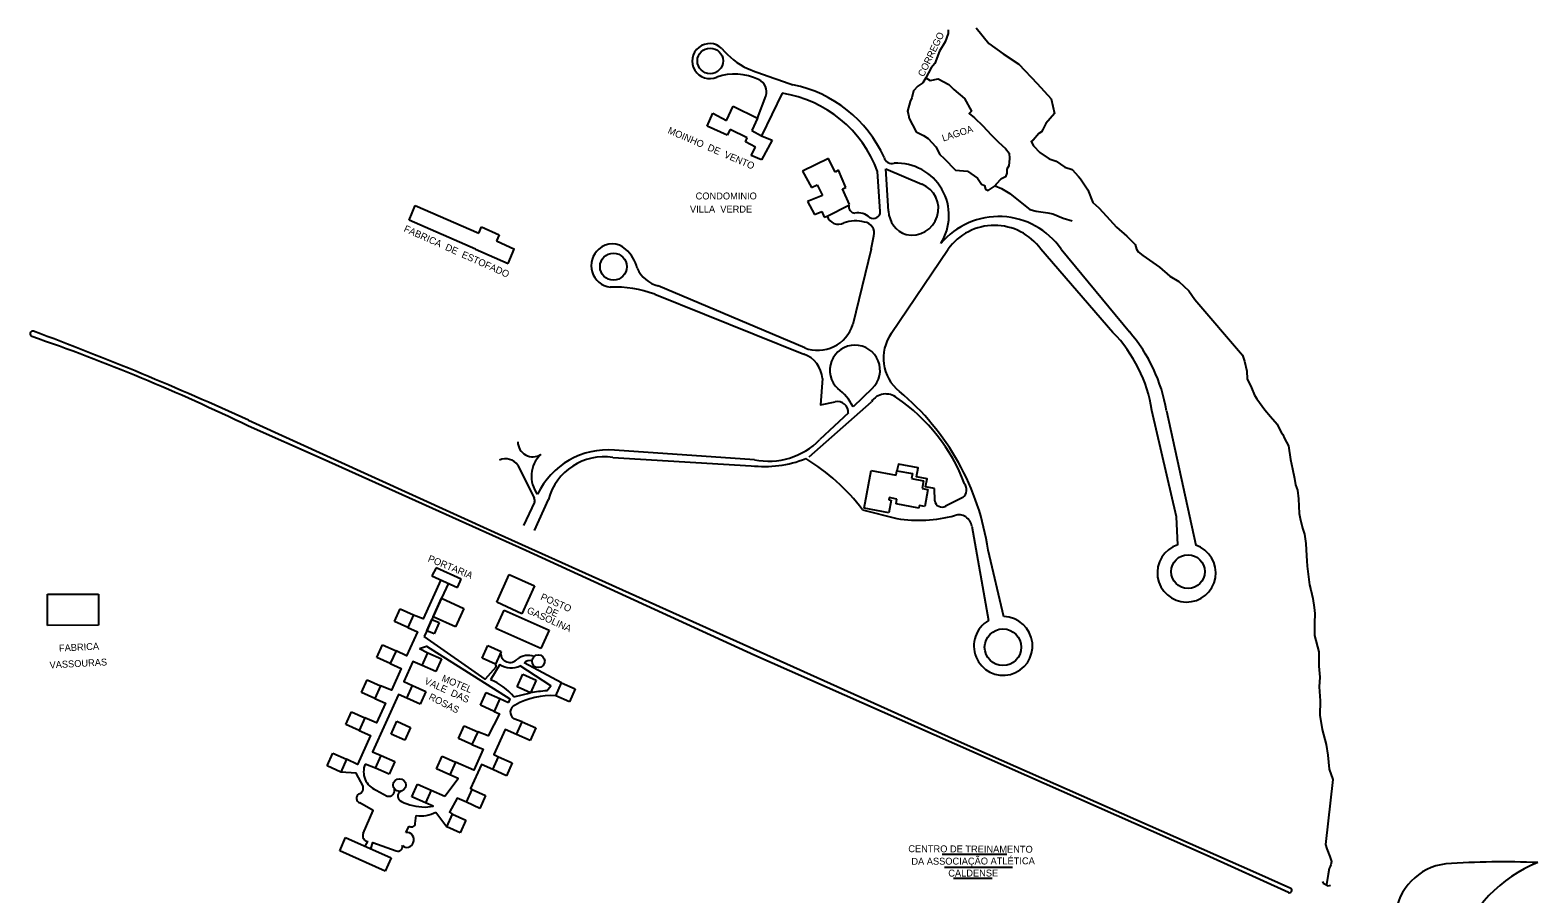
# Model space of a CAD drawing. Extents: x 325899 to 364828, y 7568995 to 7592502.
# Drawn here: x 344755 to 345627, y 7588130 to 7588628 of the extents above; entities that cross this region are included whole.
import ezdxf

# ---------------------------------------------------------------- set-up
doc = ezdxf.new("R2010")
doc.units = 0
for name, color, linetype in [('EDIFEXISTENT', 7, 'Continuous'), ('EDIFIDENTIF', 7, 'Continuous'), ('EDIFOBRAEXIS', 7, 'Continuous')]:
    doc.layers.add(name, color=color, linetype=linetype)

msp = doc.modelspace()

# ---------------------------------------------------------------- linework, layer by layer
at = {"layer": 'EDIFEXISTENT'}
for p, q in [((345157.69, 7588576.3), (345161.49, 7588584.55)), ((345161.49, 7588584.55), (345175.64, 7588577.68)), ((345146.54, 7588573.03), (345149.87, 7588580.41)), ((345149.87, 7588580.41), (345157.69, 7588576.3)), ((345175.64, 7588577.68), (345172.36, 7588570.43)), ((345158.02, 7588567.72), (345146.54, 7588573.03)), ((345159.79, 7588571.08), (345158.02, 7588567.72)), ((345169.69, 7588566.19), (345159.79, 7588571.08)), ((345172.36, 7588570.43), (345177.98, 7588567.43)), ((345177.98, 7588567.43), (345184.13, 7588564.95)), ((345168.59, 7588563.88), (345169.69, 7588566.19)), ((345174.46, 7588560.91), (345168.59, 7588563.88)), ((345171.95, 7588556.01), (345174.46, 7588560.91)), ((345184.13, 7588564.95), (345177.89, 7588553.63)), ((345177.89, 7588553.63), (345171.95, 7588556.01)), ((345216.7, 7588554.36), (345201.7, 7588547.03)), ((345220.47, 7588546.44), (345216.7, 7588554.36)), ((345201.7, 7588547.03), (345206.77, 7588537.63)), ((345222.41, 7588547.62), (345220.47, 7588546.44)), ((345226.73, 7588537.6), (345222.41, 7588547.62)), ((345213.18, 7588532.97), (345204.53, 7588529.38)), ((345206.77, 7588537.63), (345210.15, 7588539.19)), ((345210.15, 7588539.19), (345213.18, 7588532.97)), ((345224.66, 7588536.75), (345226.73, 7588537.6)), ((345228.81, 7588527.72), (345224.66, 7588536.75)), ((344974.25, 7588518.76), (344977.88, 7588527.11)), ((344977.88, 7588527.11), (345014.57, 7588511.18)), ((345204.53, 7588529.38), (345208.57, 7588521.96)), ((345208.57, 7588521.96), (345212.84, 7588523.73)), ((345212.84, 7588523.73), (345214.06, 7588520.48)), ((345215.88, 7588520.99), (345228.41, 7588527.26)), ((345228.41, 7588527.26), (345228.81, 7588527.72)), ((345012.71, 7588501.91), (344974.25, 7588518.76)), ((345014.57, 7588511.18), (345016.17, 7588514.84)), ((345016.17, 7588514.84), (345026.36, 7588510.27)), ((345214.06, 7588520.48), (345215.88, 7588520.99)), ((345026.36, 7588510.27), (345024.71, 7588506.83)), ((345024.71, 7588506.83), (345035.23, 7588501.91)), ((345012.71, 7588501.91), (345031.59, 7588493.67)), ((345031.59, 7588493.67), (345035.09, 7588501.91)), ((345237.25, 7588352.41), (345241.29, 7588374.03)), ((345241.29, 7588374.03), (345255.71, 7588371.34)), ((345255.71, 7588371.34), (345256.2, 7588373.99)), ((345256.2, 7588373.99), (345265.11, 7588372.33)), ((345265.11, 7588372.33), (345264.58, 7588369.48)), ((345264.58, 7588369.48), (345271.61, 7588368.17)), ((345271.61, 7588368.17), (345270.77, 7588363.7)), ((345251.73, 7588358.42), (345251.49, 7588357.17)), ((345256.21, 7588357.59), (345251.73, 7588358.42)), ((345270.77, 7588363.7), (345274.14, 7588363.07)), ((345274.14, 7588363.07), (345272.33, 7588353.38)), ((345251.55, 7588349.74), (345237.25, 7588352.41)), ((345251.49, 7588357.17), (345252.78, 7588356.93)), ((345252.78, 7588356.93), (345251.55, 7588349.74)), ((345255.69, 7588354.8), (345256.21, 7588357.59)), ((345268.83, 7588352.35), (345255.69, 7588354.8)), ((345269.13, 7588353.98), (345268.83, 7588352.35)), ((345272.33, 7588353.38), (345269.13, 7588353.98)), ((344989.92, 7588317.83), (344987.47, 7588313.21)), ((345004.36, 7588311.37), (344989.92, 7588317.83)), ((344987.47, 7588313.21), (345002.23, 7588306.6)), ((345002.23, 7588306.6), (345002.38, 7588306.94)), ((345002.38, 7588306.94), (345004.36, 7588311.37)), ((345025.03, 7588298.05), (345032.15, 7588313.96)), ((345032.15, 7588313.96), (345046.73, 7588307.44)), ((345046.73, 7588307.44), (345039.53, 7588291.36)), ((344765.39, 7588284.56), (344765.28, 7588302.65)), ((344765.28, 7588302.65), (344794.85, 7588302.61)), ((344794.85, 7588302.61), (344794.77, 7588284.68)), ((344988.19, 7588289.56), (344992.99, 7588300.28)), ((344992.99, 7588300.28), (345005.95, 7588294.48)), ((345039.53, 7588291.36), (345025.03, 7588298.05)), ((344965.84, 7588286.82), (344969.12, 7588294.17)), ((344969.12, 7588294.17), (344976.91, 7588290.68)), ((344976.91, 7588290.68), (344973.62, 7588283.34)), ((345001.15, 7588283.76), (344988.19, 7588289.56)), ((345005.95, 7588294.48), (345001.15, 7588283.76)), ((345024.46, 7588282.89), (345029.22, 7588293.52)), ((345029.22, 7588293.52), (345055.23, 7588281.88)), ((344794.77, 7588284.68), (344765.39, 7588284.56)), ((344973.62, 7588283.34), (344965.84, 7588286.82)), ((344984.52, 7588281.51), (344987.47, 7588288.12)), ((344988.68, 7588279.85), (344984.52, 7588281.51)), ((344987.47, 7588288.12), (344991.57, 7588286.29)), ((344991.57, 7588286.29), (344988.68, 7588279.85)), ((345050.39, 7588271.29), (345024.46, 7588282.89)), ((345055.23, 7588281.88), (345050.39, 7588271.29)), ((344955.66, 7588266.05), (344958.94, 7588273.4)), ((344958.94, 7588273.4), (344966.73, 7588269.91)), ((345016.45, 7588265.65), (345019.73, 7588273)), ((345019.73, 7588273), (345027.52, 7588269.51)), ((344963.44, 7588262.57), (344955.66, 7588266.05)), ((344966.73, 7588269.91), (344963.44, 7588262.57)), ((344981.87, 7588261.42), (344985.15, 7588268.77)), ((344985.15, 7588268.77), (344992.94, 7588265.28)), ((344992.94, 7588265.28), (344989.65, 7588257.94)), ((345024.23, 7588262.17), (345016.45, 7588265.65)), ((345027.52, 7588269.51), (345024.23, 7588262.17)), ((344989.65, 7588257.94), (344981.87, 7588261.42)), ((345036.69, 7588249.21), (345039.97, 7588256.55)), ((345039.97, 7588256.55), (345047.76, 7588253.07)), ((344946.72, 7588245.93), (344950, 7588253.28)), ((344954.5, 7588242.45), (344946.72, 7588245.93)), ((344950, 7588253.28), (344957.78, 7588249.79)), ((344957.78, 7588249.79), (344954.5, 7588242.45)), ((344972.92, 7588242.63), (344976.2, 7588249.97)), ((344976.2, 7588249.97), (344983.98, 7588246.49)), ((344983.98, 7588246.49), (344980.7, 7588239.14)), ((345015.64, 7588238.49), (345018.92, 7588245.83)), ((345018.92, 7588245.83), (345026.71, 7588242.35)), ((345044.47, 7588245.72), (345036.69, 7588249.21)), ((345047.76, 7588253.07), (345044.47, 7588245.72)), ((345059.14, 7588244.05), (345062.42, 7588251.4)), ((345062.42, 7588251.4), (345070.21, 7588247.91)), ((345070.21, 7588247.91), (345066.92, 7588240.57)), ((344980.7, 7588239.14), (344972.92, 7588242.63)), ((345023.43, 7588235), (345015.64, 7588238.49)), ((345026.71, 7588242.35), (345023.43, 7588235)), ((345066.92, 7588240.57), (345059.14, 7588244.05)), ((344937.73, 7588227.44), (344941.01, 7588234.79)), ((344945.52, 7588223.96), (344937.73, 7588227.44)), ((344941.01, 7588234.79), (344948.8, 7588231.3)), ((344948.8, 7588231.3), (344945.52, 7588223.96)), ((344963.95, 7588221.9), (344967.23, 7588229.24)), ((344967.23, 7588229.24), (344975.02, 7588225.76)), ((345036.37, 7588221.56), (345039.65, 7588228.9)), ((345039.65, 7588228.9), (345047.44, 7588225.42)), ((344971.74, 7588218.41), (344963.95, 7588221.9)), ((344975.02, 7588225.76), (344971.74, 7588218.41)), ((345002.85, 7588219.37), (345006.13, 7588226.72)), ((345010.63, 7588215.89), (345002.85, 7588219.37)), ((345006.13, 7588226.72), (345013.92, 7588223.23)), ((345013.92, 7588223.23), (345010.63, 7588215.89)), ((345044.16, 7588218.08), (345036.37, 7588221.56)), ((345047.44, 7588225.42), (345044.16, 7588218.08)), ((344926.97, 7588203.44), (344930.25, 7588210.78)), ((344930.25, 7588210.78), (344938.04, 7588207.3)), ((344934.75, 7588199.95), (344926.97, 7588203.44)), ((344938.04, 7588207.3), (344934.75, 7588199.95)), ((344954.93, 7588202.13), (344958.21, 7588209.48)), ((344962.72, 7588198.65), (344954.93, 7588202.13)), ((344958.21, 7588209.48), (344966, 7588205.99)), ((344966, 7588205.99), (344962.72, 7588198.65)), ((344990.11, 7588201.84), (344993.39, 7588209.18)), ((344997.9, 7588198.36), (344990.11, 7588201.84)), ((344993.39, 7588209.18), (345001.18, 7588205.7)), ((345001.18, 7588205.7), (344997.9, 7588198.36)), ((345022.7, 7588201.32), (345025.98, 7588208.66)), ((345030.48, 7588197.83), (345022.7, 7588201.32)), ((345025.98, 7588208.66), (345033.77, 7588205.18)), ((345033.77, 7588205.18), (345030.48, 7588197.83)), ((344975.91, 7588185.69), (344979.19, 7588193.03)), ((344979.19, 7588193.03), (344986.98, 7588189.55)), ((344983.7, 7588182.21), (344975.91, 7588185.69)), ((344986.98, 7588189.55), (344983.7, 7588182.21)), ((345007.46, 7588182.46), (345010.74, 7588189.8)), ((345010.74, 7588189.8), (345018.53, 7588186.32)), ((345018.53, 7588186.32), (345015.24, 7588178.98)), ((344996.04, 7588168.25), (344999.32, 7588175.59)), ((344999.32, 7588175.59), (345007.11, 7588172.11)), ((345015.24, 7588178.98), (345007.46, 7588182.46)), ((345003.82, 7588164.76), (344996.04, 7588168.25)), ((345007.11, 7588172.11), (345003.82, 7588164.76)), ((344934.2, 7588154.44), (344937.57, 7588162.18)), ((344937.57, 7588162.18), (344963.91, 7588150.39)), ((344960.49, 7588142.68), (344934.2, 7588154.44)), ((344963.91, 7588150.39), (344960.49, 7588142.68)), ((345502.19, 7588136.74), (345502.56, 7588135.78)), ((345502.56, 7588135.78), (345505.45, 7588134.28)), ((345505.45, 7588134.28), (345506.79, 7588134.62))]:
    msp.add_line(p, q, dxfattribs=at)
for centre in [(345049.04, 7588263.97), (344968.74, 7588192.42)]:
    msp.add_circle(centre, 3.67, dxfattribs=at)
at = {"layer": 'EDIFIDENTIF'}
msp.add_circle((345148.29, 7588610.68), 7.4, dxfattribs=at)
at = {"layer": 'EDIFOBRAEXIS'}
for points in [[(345285.76, 7588628.53), (345285.77, 7588626.47), (345284, 7588621.78), (345280.77, 7588616.26), (345278.09, 7588609.17), (345275.9, 7588606.69), (345272.9, 7588600.82), (345275.44, 7588599.31), (345279.95, 7588600.26), (345286.24, 7588597.06), (345288.98, 7588594.21), (345295.33, 7588589.01), (345299.32, 7588581.66), (345298, 7588580.34), (345301.07, 7588577.7), (345305.92, 7588573.26), (345310.72, 7588567.98), (345314.94, 7588563.78), (345318.97, 7588560.01), (345321.12, 7588557.48), (345321.28, 7588554.23), (345320.92, 7588550.01), (345319.71, 7588548.13), (345319.72, 7588545.92), (345318.87, 7588543.72), (345316.25, 7588542.35), (345315.73, 7588541.71), (345314.06, 7588540.05), (345313.28, 7588539.27), (345312.99, 7588538.43), (345316.6, 7588536.99), (345321.43, 7588534.08), (345328.44, 7588528.56), (345333.06, 7588524.85), (345336.74, 7588523.9), (345343.36, 7588522.97), (345346.37, 7588522.39), (345352.19, 7588519.85), (345357.55, 7588518.34)], [(345301.98, 7588629.7), (345309.34, 7588620.68), (345317.55, 7588614.67), (345326.63, 7588608.73), (345337.22, 7588597.63), (345345.28, 7588588.72), (345347.16, 7588580.21), (345342.25, 7588574.46), (345340.51, 7588570.97), (345339.82, 7588569.68), (345338.13, 7588568.74), (345334.9, 7588564.92), (345334.55, 7588564.63), (345333.82, 7588564.06), (345335.16, 7588561.6), (345338.79, 7588557.69), (345344.19, 7588554.08), (345348.13, 7588552.72), (345353.22, 7588549.23), (345357.44, 7588547.98), (345361.09, 7588543.95), (345362.21, 7588542.47), (345366.46, 7588536.29), (345369.36, 7588528.89), (345372.85, 7588525.85), (345377.36, 7588521), (345383.11, 7588514.72), (345389.05, 7588509.54), (345393.89, 7588504.56), (345394.61, 7588501.91), (345394.61, 7588501.91)], [(345272.9, 7588600.82), (345271.1, 7588597.99), (345268.33, 7588596.04), (345265.76, 7588593.35), (345264.74, 7588589.31), (345263.89, 7588587.19), (345262.36, 7588581.72), (345262.88, 7588579.62), (345263.35, 7588577.37), (345265.16, 7588573.76), (345267.4, 7588569.63), (345271.53, 7588567.67), (345274.33, 7588565.82), (345278.66, 7588560.99), (345280.9, 7588556.63), (345283.58, 7588554.21), (345290.05, 7588547.53), (345297, 7588547.02), (345302.74, 7588543.03), (345305.14, 7588539.44), (345306.79, 7588538.63), (345307.46, 7588536.5), (345308.92, 7588535.82), (345312.99, 7588538.43)], [(345175.64, 7588577.68), (345180.5, 7588590.38)], [(345189.88, 7588591.97), (345177.98, 7588567.43)], [(345246.6, 7588523.61), (345245.05, 7588546.72)], [(345249.82, 7588548.33), (345270.55, 7588539.49)], [(345251.34, 7588523.88), (345249.82, 7588548.33)], [(345241.34, 7588501.91), (345242.83, 7588509.71)], [(345241.34, 7588501.91), (345230.69, 7588458.43)], [(345252.92, 7588453.3), (345285.78, 7588501.91)], [(345381.02, 7588453.89), (345339.35, 7588501.91)], [(345351.11, 7588501.91), (345390.53, 7588454.21)], [(345394.61, 7588501.91), (345395.62, 7588500.41), (345398.25, 7588498.33), (345407.91, 7588491.57), (345413.81, 7588486.38), (345419.06, 7588483.28), (345424.89, 7588477.81), (345428.28, 7588472.88), (345455.85, 7588440.8), (345457.03, 7588437.17), (345458.36, 7588431.43), (345458.53, 7588426.98), (345461.13, 7588421.94), (345462.85, 7588417.53), (345464.17, 7588415.55), (345468.84, 7588409.13), (345471.98, 7588405.37), (345475.84, 7588400.95), (345478.52, 7588395.2), (345479.13, 7588394.93), (345480.15, 7588392.67), (345482.45, 7588388.29), (345483.68, 7588380.52), (345484.8, 7588375.16), (345485.95, 7588369.44), (345486.59, 7588365.78), (345487.59, 7588362.79), (345488.33, 7588357.68), (345488.69, 7588349.26), (345489.3, 7588346.46), (345490.55, 7588340.85), (345491.63, 7588337.37), (345492.45, 7588331.96), (345492.92, 7588324.86), (345493.03, 7588321.88), (345493.19, 7588318.78), (345493.87, 7588314.23), (345494.56, 7588308.03), (345495.43, 7588305.11), (345496.6, 7588300.13), (345497.26, 7588295.02), (345497.78, 7588291.59), (345497.4, 7588285.98), (345497.57, 7588278.78), (345499.96, 7588269.39), (345500.09, 7588261.17), (345500.56, 7588254.83), (345500.15, 7588249.23), (345500.77, 7588241.14), (345500.67, 7588232.74), (345501.97, 7588224.43), (345504.22, 7588215.9), (345505.25, 7588209.67), (345505.96, 7588201.66), (345508.13, 7588195.57), (345503.89, 7588158.09), (345504.71, 7588155.68), (345506.28, 7588151.16), (345507.27, 7588148.3), (345506.88, 7588146.28), (345506.49, 7588145.39), (345506.01, 7588144.14), (345505.43, 7588140.97), (345504.46, 7588134.94), (345504.46, 7588134.94)], [(345202.88, 7588444.94), (345118.22, 7588480.7)], [(345116.2, 7588475.9), (345202.4, 7588441.24)], [(345213.12, 7588427.26), (345212.05, 7588412), (345220.56, 7588413.84)], [(345241.94, 7588421.51), (345230.82, 7588410.83)], [(345205.55, 7588382.05), (345241.41, 7588413.86)], [(344881.39, 7588403.14), (345025.72, 7588337.48), (345293.6, 7588217.05), (345463.58, 7588141.91), (345483.86, 7588132.84)], [(345228.11, 7588407.42), (345211.61, 7588391.94)], [(345418.54, 7588331.11), (345417.67, 7588347.42), (345403.55, 7588408.8)], [(345411.93, 7588408.58), (345428.9, 7588331.01)], [(345482.39, 7588130.34), (345434.87, 7588151.92), (345174.01, 7588267.28), (345041.67, 7588327.94), (344924.14, 7588380.88), (344881.39, 7588399.73)], [(345173.8, 7588380.34), (345093, 7588385.84)], [(345037.11, 7588377.13), (345046.54, 7588358.13)], [(345092.05, 7588381.58), (345171.97, 7588376.89)], [(345277.99, 7588363.72), (345272.77, 7588364.69), (345273.62, 7588369.22), (345267.47, 7588370.37), (345268.44, 7588375.57), (345257.04, 7588377.7), (345256.2, 7588373.99)], [(345278.01, 7588356.62), (345277.99, 7588363.72)], [(345294.28, 7588358.59), (345284.35, 7588353.42)], [(345046.77, 7588355.76), (345040.31, 7588342.38)], [(345046.78, 7588339.43), (345054.89, 7588357.44)], [(345236.34, 7588351.48), (345256.14, 7588346.36)], [(345299.46, 7588341.91), (345309.18, 7588287.43)], [(345318.04, 7588289.68), (345308.83, 7588328.16)], [(344992.61, 7588310.91), (344982.47, 7588288.49), (344976.9, 7588290.63)], [(344996.97, 7588308.95), (344992.99, 7588300.28), (344987.47, 7588288.12), (344984.52, 7588281.51), (344983.07, 7588278.32)], [(344973.62, 7588283.34), (344979.08, 7588280.87), (344972.82, 7588267.03), (344966.73, 7588269.91)], [(344980.29, 7588271.24), (344984.43, 7588272.58), (345032.42, 7588242.27), (345031.71, 7588240.09)], [(344980.29, 7588271.24), (344985.15, 7588268.77)], [(345024.38, 7588260.52), (345018.29, 7588253.51), (344983.07, 7588278.32)], [(344963.44, 7588262.57), (344969.75, 7588259.72), (344964.1, 7588247.22), (344957.78, 7588249.79)], [(344981.87, 7588261.42), (344976.49, 7588263.86), (344971.26, 7588252.28), (344976.2, 7588249.97)], [(345062.42, 7588251.4), (345040.85, 7588263.02)], [(345026.73, 7588262.02), (345021.34, 7588253.24)], [(345053.84, 7588246.86), (345056.17, 7588249.81), (345038.55, 7588261.32)], [(344972.92, 7588242.63), (344968.1, 7588244.8), (344953.05, 7588211.53), (344958.21, 7588209.48)], [(345034.88, 7588243.47), (345044.47, 7588245.72)], [(344954.5, 7588242.45), (344960.59, 7588239.7), (344955.48, 7588228.41), (344948.8, 7588231.3)], [(345026.71, 7588242.35), (345031.71, 7588240.09)], [(345023.43, 7588235), (345026.61, 7588233.64), (345020.04, 7588220.9), (345013.92, 7588223.23)], [(345039.65, 7588228.9), (345034.88, 7588230.74)], [(344945.52, 7588223.96), (344952.05, 7588221.01), (344944.49, 7588204.3), (344938.04, 7588207.3)], [(345036.37, 7588221.56), (345029.83, 7588224.52), (345023.32, 7588210.12), (345025.98, 7588208.66)], [(345010.63, 7588215.89), (345017.05, 7588213.13), (345011.67, 7588200.99), (345001.18, 7588205.7)], [(344954.93, 7588202.13), (344948.87, 7588204.58)], [(345022.7, 7588201.32), (345016.1, 7588204.3), (345009.83, 7588190.44), (345010.74, 7588189.8)], [(344947.67, 7588191.73), (344943.73, 7588199.23), (344934.75, 7588199.95)], [(344994.89, 7588185.97), (345002.61, 7588196.22), (344997.9, 7588198.36)], [(344955.23, 7588189.49), (344961.7, 7588186.04)], [(344986.98, 7588189.55), (344994.89, 7588185.97)], [(345007.46, 7588182.46), (345002.11, 7588184.87), (344997.57, 7588176.84), (344999.32, 7588175.59)], [(344947.83, 7588164.37), (344953.56, 7588177.64), (344945.81, 7588182.09)], [(344983.49, 7588179.7), (344988.2, 7588180.14), (344983.7, 7588182.21)], [(344989.71, 7588176.82), (344996.04, 7588168.25)], [(344972.37, 7588164.99), (344974.26, 7588168.7)], [(344977.86, 7588170.16), (344978.38, 7588174.78)], [(344948.95, 7588157.09), (344950.37, 7588159.92)], [(344952.13, 7588155.66), (344953.28, 7588159.33), (344966.82, 7588154.43)], [(345282.3, 7588152.43), (345319.69, 7588152.43)], [(345283.63, 7588144.95), (345322.92, 7588144.95)], [(345288.92, 7588138.63), (345311.25, 7588138.63)]]:
    msp.add_lwpolyline(points, dxfattribs=at)
for centre, radius in [((345092.38, 7588491.83), 7.76), ((345424.4, 7588315.7), 9.73), ((345317.48, 7588272.01), 10.6)]:
    msp.add_circle(centre, radius, dxfattribs=at)
for centre, radius, start, end in [((345147.99, 7588610.59), 10.12, 46.03268, 294.01233), ((345188.23, 7588644.97), 42.86, 219.20323, 244.56676), ((345162.44, 7588570.35), 32.66, 64.91761, 108.43206), ((345392.55, 7589189.34), 624.18, 249.09402, 251.65702), ((345172.84, 7588592.71), 8, 343.10031, 64.54014), ((345181.19, 7588524.06), 74.34, 24.6302, 78.41161), ((345179.28, 7588522.79), 69.99, 19.99599, 81.28925), ((345253.27, 7588555.91), 4.59, 190.94063, 287.52506), ((345256.07, 7588521.39), 30.18, 327.39844, 92.70588), ((345264.9, 7588525.29), 15.28, 257.49473, 68.31362), ((345232.24, 7588526.57), 3.89, 169.7853, 264.54072), ((345242.69, 7588523.56), 3.91, 236.78135, 0.85547), ((345266.05, 7588524.4), 14.72, 182.01248, 252.35369), ((345222.34, 7588523.16), 6.81, 198.55205, 297.6243), ((345232.18, 7588498.21), 20.06, 74.684, 109.45111), ((345233.8, 7588512.83), 10.05, 47.84917, 101.08842), ((345236.77, 7588511.32), 6.28, 345.18709, 83.50259), ((345315.07, 7588476.9), 43.87, 34.76169, 139.93912), ((345312.56, 7588482.73), 32.94, 35.60428, 144.39572), ((345092.01, 7588492.38), 12.47, 130.10295, 263.34076), ((345091.7, 7588493.87), 11.15, 46.16502, 133.83498), ((345084.93, 7588485.45), 21.93, 14.46037, 48.63024), ((345122.85, 7588498.37), 18.26, 204.03215, 255.31341), ((345093.29, 7588414.81), 65.24, 69.43853, 92.39807), ((344756.92, 7588452.93), 1.61, 75.94172, 243.80818), ((344130.95, 7586765.26), 1801.62, 65.38395, 69.65567), ((345210.49, 7588464.66), 21.14, 248.90053, 342.85979), ((345321.32, 7588395.88), 83.24, 8.93076, 44.17875), ((345320.87, 7588393.72), 92.26, 9.26573, 40.97011), ((344392.85, 7587395.45), 1116.8, 64.0587, 71.01282), ((345231.95, 7588432.02), 14.5, 313.53867, 227.13863), ((345273.12, 7588439.04), 24.73, 144.77675, 231.08217), ((345197.29, 7588426.22), 15.86, 3.7512, 71.23996), ((345205.15, 7588398.48), 28.49, 25.69185, 53.51063), ((345164.48, 7588307.59), 145.81, 8.10894, 50.31426), ((345221.71, 7588407.54), 6.4, 358.90514, 100.33963), ((345249.73, 7588408.31), 10, 50.15157, 146.30287), ((345197.92, 7588329.81), 104, 20.64724, 55.96037), ((345045.8, 7588390.71), 8.69, 180.27509, 302.30512), ((345089.22, 7588340.85), 45.15, 85.19222, 154.39965), ((345182.09, 7588420.76), 41.26, 258.4084, 315.68432), ((345029.98, 7588372.18), 8.68, 34.75523, 113.67323), ((345062.12, 7588370.8), 17.15, 132.88935, 217.4738), ((345086.79, 7588349.01), 32.99, 80.82026, 165.19473), ((345179.71, 7588440.84), 64.42, 263.09968, 291.64191), ((345142.48, 7588279.91), 118.03, 37.32443, 58.88633), ((345044.74, 7588356.76), 2.26, 333.69126, 37.25991), ((345290.89, 7588363.01), 5.57, 307.43823, 38.57085), ((345282.36, 7588357.35), 4.41, 189.5986, 296.92029), ((345268.8, 7588424.55), 79.21, 260.80599, 285.22517), ((345291.93, 7588340.9), 7.59, 7.63415, 107.9082), ((345423.56, 7588314.99), 16.89, 107.3003, 71.56562), ((345317.62, 7588272.75), 16.94, 119.9033, 88.59086), ((345023.11, 7588261.24), 1.46, 330.52769, 39.8316), ((345032.59, 7588268.67), 5.4, 178.63712, 320.39743), ((345043, 7588256.82), 10.47, 70.15691, 126.62408), ((345044.02, 7588259.89), 4.46, 72.26869, 135.26747), ((345033.25, 7588271.96), 11.88, 236.73355, 296.49412), ((345006.62, 7588218.58), 37.65, 41.37157, 66.98517), ((345062.37, 7588137.55), 109.64, 94.46642, 99.39639), ((345037.21, 7588234.55), 4.46, 112.70461, 238.48985), ((345056.87, 7588199.42), 44.69, 87.08817, 118.58463), ((344959.42, 7588200.14), 11.44, 157.1934, 248.52014), ((344946.95, 7588184.89), 3.02, 124.29193, 247.81312), ((344944.49, 7588190.66), 3.36, 283.07196, 18.59959), ((344962.58, 7588189.28), 3.36, 254.83847, 16.56729), ((344970.96, 7588185.96), 3.21, 115.69963, 249.1676), ((344984.21, 7588212.95), 33.27, 244.35417, 268.75481), ((344980.85, 7588193.49), 18.88, 262.47339, 297.98568), ((344975.66, 7588170.43), 2.22, 231.00939, 353.15385), ((344950.59, 7588162.99), 3.08, 153.40809, 265.92966), ((344973.03, 7588160.17), 3.73, 224.8152, 343.71023), ((344973.07, 7588161.03), 4.02, 331.7004, 100.06905), ((344967.84, 7588156.85), 2.63, 247.20558, 15.17875), ((345577.23, 7588113.86), 33.22, 96.68057, 175.07599), ((345606.69, 7587684.81), 463.25, 87.54154, 94.12478), ((345656.14, 7588073.16), 80.13, 111.66152, 160.72729), ((345482.94, 7588131.7), 1.46, 248.06233, 50.97278)]:
    msp.add_arc(centre, radius, start, end, dxfattribs=at)

# ---------------------------------------------------------------- texts
at = {"layer": 'EDIFIDENTIF'}
for s, rotation, p in [('CORREGO', 64.34392, (345271.68, 7588601.18)), ('MOINHO  DE  VENTO', 336.79817, (345123.38, 7588569.04)), ('LAGOA', 17.9928, (345282.98, 7588564.06)), ('CONDOMINIO', 0.03215, (345139.87, 7588530.65)), ('VILLA  VERDE', 359.97621, (345136.58, 7588523.08)), ('FABRICA  DE  ESTOFADO', 335.8582, (344970.87, 7588512.34)), ('PORTARIA', 337.57571, (344984.81, 7588321.75)), ('POSTO', 336.47209, (345049.85, 7588299.66)), ('GASOLINA', 335.69916, (345042, 7588291.92)), ('DE', 335.83508, (345052.7, 7588292.31)), ('FABRICA', 3.07246, (344772.06, 7588269.46)), ('VASSOURAS', 3.07246, (344766.61, 7588259.76)), ('VALE  DAS', 335.64958, (344982.78, 7588251.08)), ('MOTEL', 336.98475, (344992.73, 7588252.65)), ('ROSAS', 333.2288, (344985.24, 7588242.09)), ('CENTRO DE TREINAMENTO', 359.74049, (345262.76, 7588153.67)), ('DA ASSOCIAÇÃO ATLÉTICA', 0.24854, (345264.53, 7588146.37)), ('CALDENSE', 0.11503, (345285.87, 7588139.57))]:
    msp.add_text(s, height=4, rotation=rotation, dxfattribs=at).set_placement(p)

doc.saveas('drawing.dxf')
